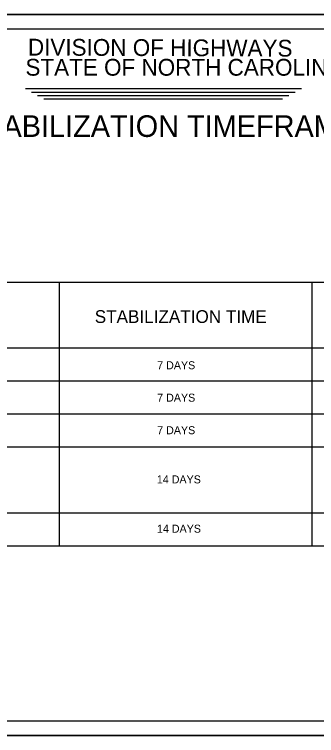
# Model space of a CAD drawing. Extents: x 1676398 to 1678098, y 1329391 to 1330491.
# Drawn here: x 1676983 to 1677444, y 1329391 to 1330491 of the extents above; entities that cross this region are included whole.
import ezdxf

# ---------------------------------------------------------------- set-up
doc = ezdxf.new("R2010")
doc.units = 0
for name, color, linetype in [('Sheet Plan CELL', 7, 'Continuous'), ('Sheet Plot Border Outside CELL', 7, 'Continuous'), ('Stabilization Guidelines Sheet CELL', 7, 'Continuous'), ('z - Construction', 7, 'Continuous')]:
    doc.layers.add(name, color=color, linetype=linetype)

msp = doc.modelspace()

# ---------------------------------------------------------------- linework, layer by layer
at = {"layer": 'Sheet Plan CELL'}
for p, q in [((1678084.8, 1330468.2), (1676434.8, 1330468.2)), ((1676434.8, 1329413.3), (1678084.8, 1329413.3))]:
    msp.add_line(p, q, dxfattribs=at)
at = {"layer": 'Sheet Plot Border Outside CELL'}
msp.add_lwpolyline([(1676398.4, 1330490.7), (1678098.3, 1330490.7), (1678098.3, 1329390.8), (1676398.4, 1329390.8)], close=True, dxfattribs=at)
at = {"layer": 'Stabilization Guidelines Sheet CELL'}
for p, q in [((1677000, 1330377.6), (1677421.2, 1330377.6)), ((1677009.2, 1330372.4), (1677411.5, 1330372.4)), ((1677018.4, 1330367), (1677401.9, 1330367)), ((1677028.1, 1330362.1), (1677392.2, 1330362.1)), ((1677052, 1329680.2), (1677052, 1330082.6)), ((1677437.2, 1330082.6), (1677437.2, 1329680.4)), ((1676490.7, 1329982), (1677930, 1329982)), ((1676490.7, 1329931.7), (1677930, 1329931.7)), ((1676490.7, 1329881.5), (1677930, 1329881.5)), ((1676490.7, 1329831.2), (1677930, 1329831.2)), ((1676490.7, 1329730.5), (1677930, 1329730.5)), ((1676490.7, 1329680.2), (1677930, 1329680.2))]:
    msp.add_line(p, q, dxfattribs=at)
msp.add_lwpolyline([(1676490.7, 1329680.2), (1676490.7, 1330082.6), (1677930, 1330082.6), (1677930, 1329680.2)], dxfattribs=at)
at = {"layer": 'z - Construction'}
for p, q in [((1678098.3, 1330490.7), (1676398.4, 1330490.7)), ((1676398.4, 1329390.8), (1678098.3, 1329390.8))]:
    msp.add_line(p, q, dxfattribs=at)

# ---------------------------------------------------------------- texts
at = {"layer": 'Stabilization Guidelines Sheet CELL'}
for s, height, rotation, p in [('  DIVISION OF HIGHWAYS', 25.639, 359.7699, (1676984.5, 1330428.1)), ('STATE OF NORTH CAROLINA', 25.639, 360, (1676999.8, 1330397.3)), ('SOIL STABILIZATION TIMEFRAMES', 32.964, 360, (1676795.8, 1330303.9)), ('STABILIZATION TIME', 19.524, 360, (1677105.6, 1330020.1)), ('7 DAYS', 12.21, 360, (1677200.9, 1329949.5)), ('7 DAYS', 12.21, 360, (1677200.9, 1329900.1)), ('7 DAYS', 12.21, 360, (1677200.9, 1329850.4)), ('14 DAYS', 12.21, 360, (1677200.4, 1329775.4)), ('14 DAYS', 12.21, 360, (1677200.6, 1329700.2))]:
    msp.add_text(s, height=height, rotation=rotation, dxfattribs=at).set_placement(p)

doc.saveas('drawing.dxf')
